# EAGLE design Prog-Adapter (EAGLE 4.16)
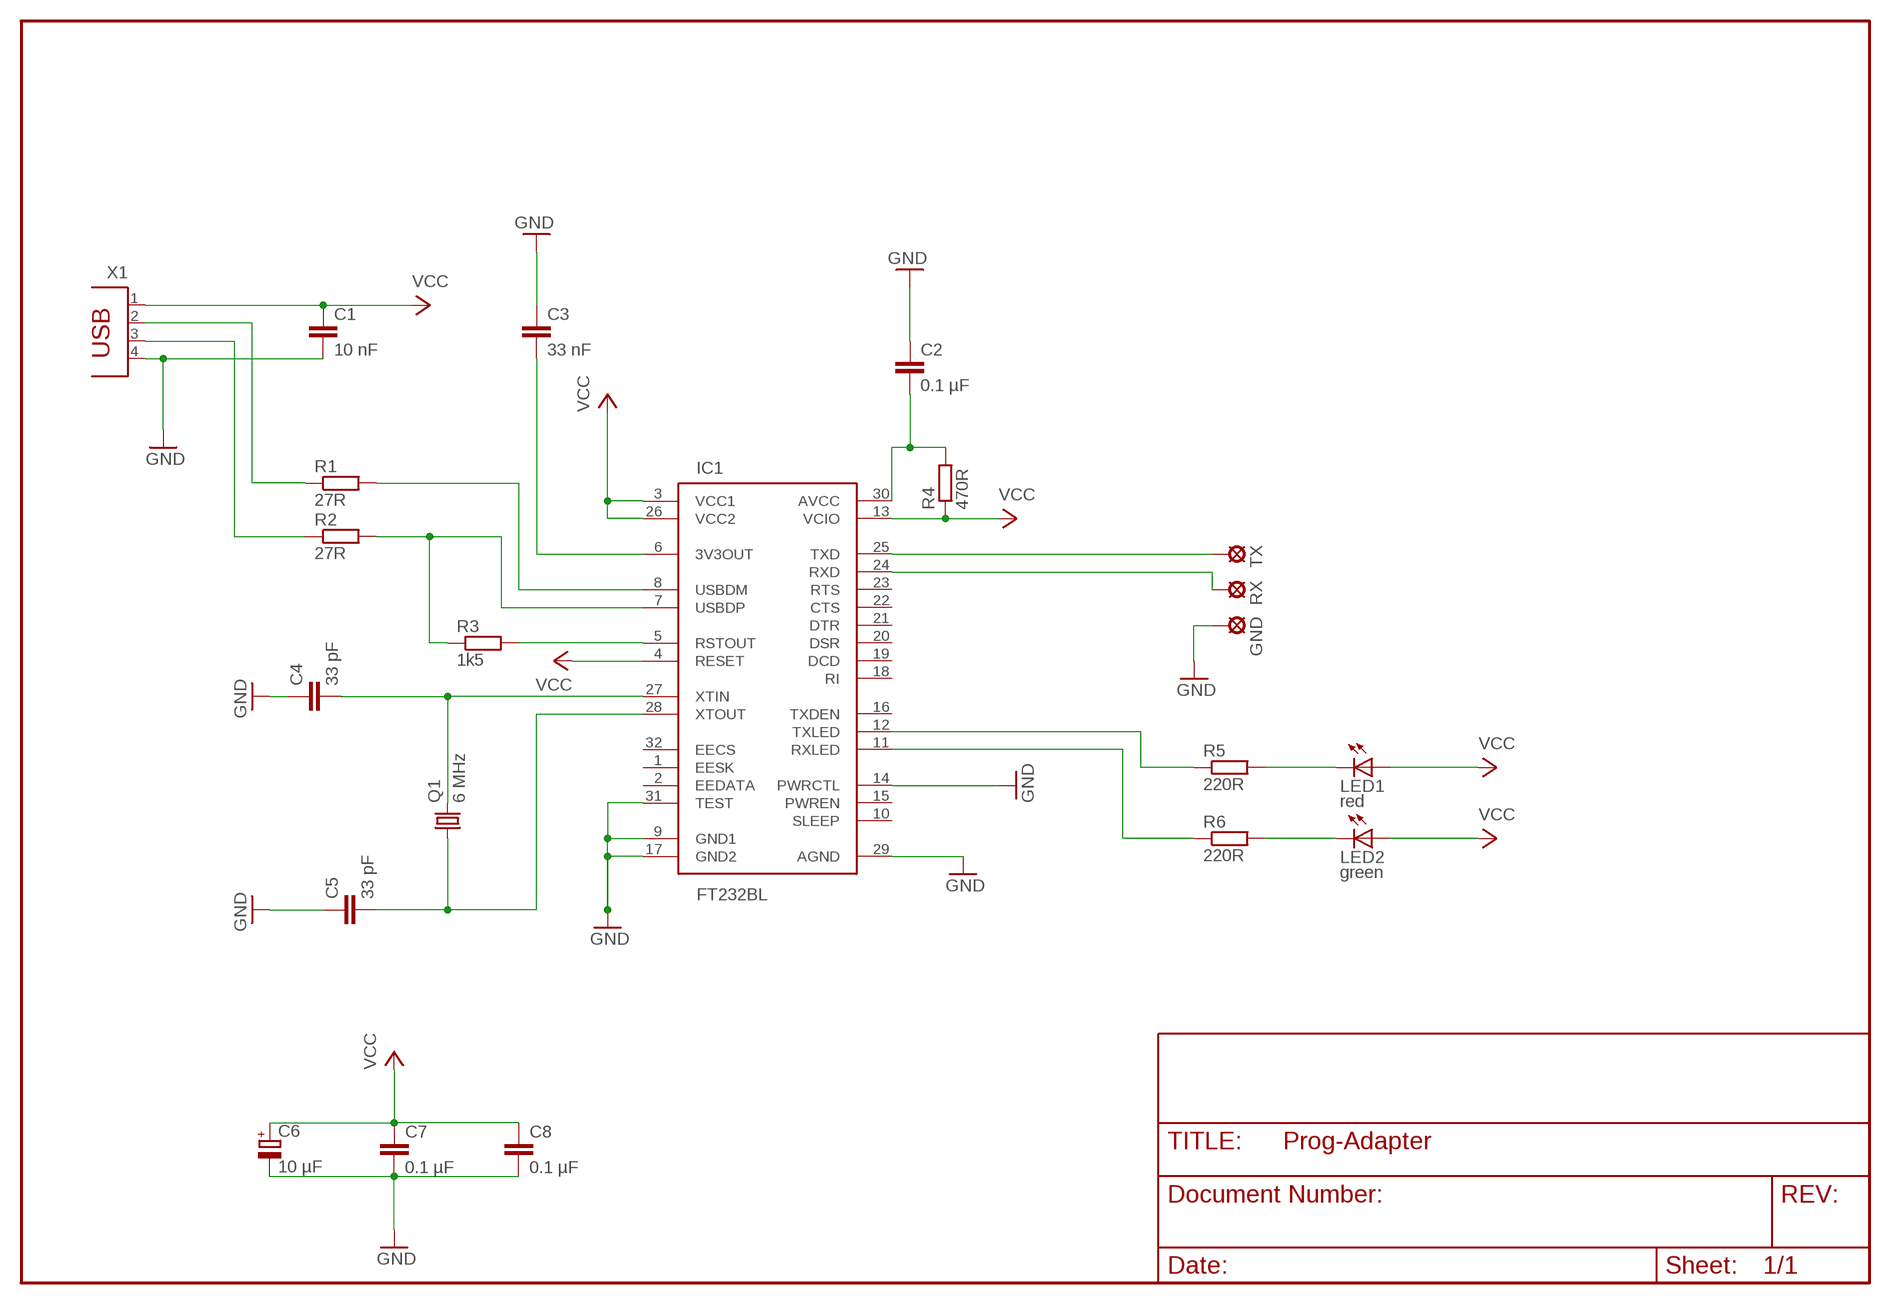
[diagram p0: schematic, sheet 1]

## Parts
C1  10 nF  C-EUC1206  [C1206]
C2  0.1 µF  C-EUC1206  [C1206]
C3  33 nF  C-EUC1206  [C1206]
C4  33 pF  C-EUC1206  [C1206]
C5  33 pF  C-EUC1206  [C1206]
C6  10 µF  CPOL-EUSMCC  [SMC_C]
C7  0.1 µF  C-EUC1206  [C1206]
C8  0.1 µF  C-EUC1206  [C1206]
GND  LSP10  [LSP10]
IC1  FT232BL  FT232BM  [QFP-32]
LED1  red  LED3MM  [LED3MM]
LED2  green  LED3MM  [LED3MM]
Q1  6 MHz  CRYTALHC49S  [HC49/S]
R1  27R  R-EU_M1206  [M1206]
R2  27R  R-EU_M1206  [M1206]
R3  1k5  R-EU_M1206  [M1206]
R4  470R  R-EU_M1206  [M1206]
R5  220R  R-EU_M1206  [M1206]
R6  220R  R-EU_M1206  [M1206]
RX  LSP10  [LSP10]
TX  LSP10  [LSP10]
X1  PN61729  [PN61729]

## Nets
GND: C1.2 C2.1 C3.1 C4.1 C5.1 C6.- C7.2 C8.2 GND.MP IC1.9(GND1) IC1.14(PWRCTL) IC1.17(GND2) IC1.29(AGND) IC1.31(TEST) X1.4
N$1: IC1.24(RXD) RX.MP
N$2: IC1.25(TXD) TX.MP
N$3: IC1.8(USBDM) R1.2
N$4: R2.1 X1.3
N$5: R1.1 X1.2
N$6: IC1.7(USBDP) R2.2 R3.1
N$7: IC1.5(RSTOUT) R3.2
N$8: C2.2 IC1.30(AVCC) R4.2
N$9: C3.2 IC1.6(3V3OUT)
N$10: C4.2 IC1.27(XTIN) Q1.2
N$11: LED1.K(C) R5.2
N$12: C5.2 IC1.28(XTOUT) Q1.1
N$13: LED2.K(C) R6.2
N$14: IC1.12(TXLED) R5.1
N$15: IC1.11(RXLED) R6.1
VCC: C1.1 C6.+ C7.1 C8.1 IC1.3(VCC1) IC1.4(RESET) IC1.13(VCIO) IC1.26(VCC2) LED1.A LED2.A R4.1 X1.1
Unconnected: IC1.1(EESK) IC1.2(EEDATA) IC1.10(SLEEP) IC1.15(PWREN) IC1.16(TXDEN) IC1.18(RI) IC1.19(DCD) IC1.20(DSR) IC1.21(DTR) IC1.22(CTS) IC1.23(RTS) IC1.32(EECS)

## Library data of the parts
C1-C5 C7 C8 = rcl:C-EU: CAPACITOR, European symbol
C6 = rcl:CPOL-EU: POLARIZED CAPACITOR, European symbol
GND RX TX = solpad:LSP10: SOLDER PAD
IC1 = FTDI:FT232BM: FT232BM USB-RS232 Wandler FTDI
LED1 LED2 = led:LED: LED
Q1 = crystal:CRYTAL: CRYSTAL
R1-R6 = rcl:R-EU_: RESISTOR, European symbol
X1 = con-berg:PN61729: BERG USB connector

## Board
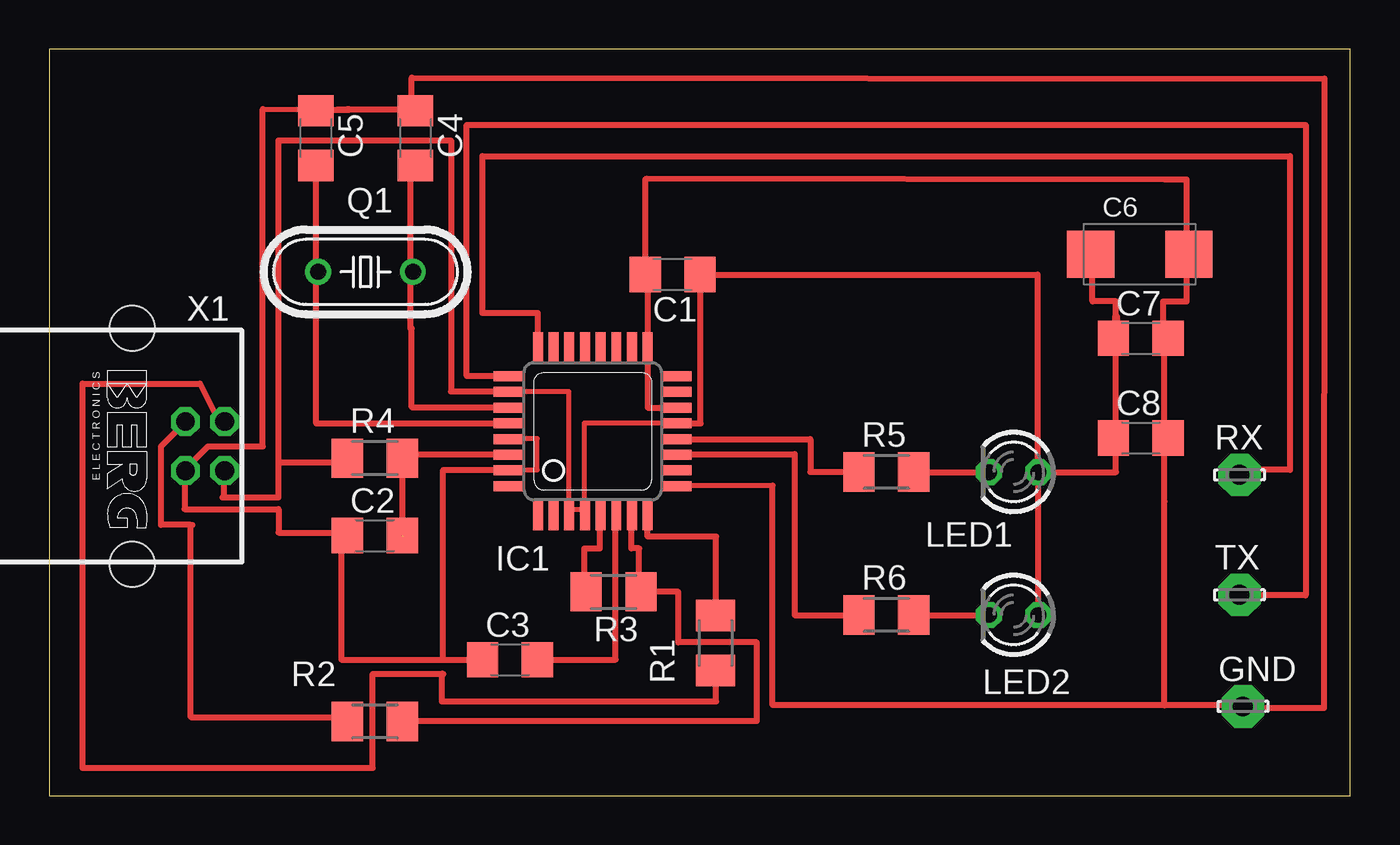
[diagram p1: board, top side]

Size 66.4 x 38.08 mm. Coordinates in mm from the lower left corner, seen from the top.
Outline: 0,0 66.4,0 66.4,38.08 0,38.08 0,0
Copper layers (1*16): Top 0.035mm / dielectric 1.5mm / Bottom 0.035mm
Design rules "default": minimum track width 10mil, minimum drill 24mil, track to track 8mil, track to pad 8mil, pad to pad 8mil, via to via 8mil, smd to smd 8mil, copper to edge 40mil, drill to drill 8mil, minimum pad ring 10mil, minimum via ring 8mil, stop-mask expansion 4mil, vias tented up to drill 0mil, thermal gap 10mil

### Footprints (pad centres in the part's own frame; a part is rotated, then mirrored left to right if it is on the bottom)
C1206 = smd 1.6 x 1.8: 1 -1.4,0; 2 1.4,0
SMC_C = smd 2.4 x 2.4: + -2.5,0; - 2.5,0
LSP10 = drill 1.016 pad 2.159 octagon: MP 0,0
QFP-32 = smd 0.508 x 1.6: 1 -2.8,-4.25; 2 -2,-4.25; 3 -1.2,-4.25; 4 -0.4,-4.25; 5 0.4,-4.25; 6 1.2,-4.25; 7 2,-4.25; 8 2.8,-4.25; 17 2.8,4.25; 18 2,4.25; 19 1.2,4.25; 20 0.4,4.25; 21 -0.4,4.25; 22 -1.2,4.25; 23 -2,4.25; 24 -2.8,4.25 | smd 1.6 x 0.508: 9 4.25,-2.8; 10 4.25,-2; 11 4.25,-1.2; 12 4.25,-0.4; 13 4.25,0.4; 14 4.25,1.2; 15 4.25,2; 16 4.25,2.8; 25 -4.25,2.8; 26 -4.25,2; 27 -4.25,1.2; 28 -4.25,0.4; 29 -4.25,-0.4; 30 -4.25,-1.2; 31 -4.25,-2; 32 -4.25,-2.8
LED3MM = drill 0.813 octagon: A -1.27,0; K 1.27,0
HC49/S = drill 0.813 round: 1 -2.413,0; 2 2.413,0
M1206 = smd 1.6 x 2: 1 -1.4,0; 2 1.4,0
PN61729 = drill 0.95 octagon: 1 1.25,4.71; 2 -1.25,4.71; 3 -1.25,2.71; 4 1.25,2.71 | hole 2.3: -6.02,0; 6.02,0

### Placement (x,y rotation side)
C1  31.81,26.58 180 top
C2  16.62,13.27 0 top
C3  23.52,6.94 0 top
C4  18.69,33.54 270 top
C5  13.61,33.54 270 top
C6  55.64,27.61 0 top
C7  55.7,23.33 0 top
C8  55.7,18.25 0 top
GND  60.91,4.55 0 top
IC1  27.74,18.59 0 top
LED1  49.21,16.51 180 top
LED2  49.21,9.22 180 top
Q1  16.15,26.72 0 top
R1  34,7.79 90 top
R2  16.62,3.79 0 top
R3  28.8,10.4 180 top
R4  16.62,17.22 0 top
R5  42.72,16.51 0 top
R6  42.72,9.22 0 top
RX  60.73,16.37 0 top
TX  60.73,10.25 0 top
X1  4.25,17.83 270 top

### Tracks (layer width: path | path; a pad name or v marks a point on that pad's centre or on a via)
GND
  Top 0.254: IC1.9 32.51,15.82 36.91,15.82 | 56.91,23.42 C7.2 | IC1.29 24.11,18.22 24.91,18.22 24.91,16.62 24.11,16.62 IC1.31 22.91,16.62 | C5.1 15.31,34.94 15.31,35.02 10.91,35.02 | 7.31,17.02 X1.4 6.91,16.58 | C2.1 14.51,13.42 | C2.1 14.91,12.62 | C2.1 14.91,13.27 14.91,13.42
  Top 0.305: 36.91,15.82 36.91,4.62 56.91,4.62 56.91,4.61 | C7.2 56.91,23.33 56.91,23.42 | 56.91,23.42 56.91,23.82 | 56.91,18.25 C8.2 | 56.91,18.25 56.91,23.42 | 56.91,4.61 56.91,18.25 | 56.91,4.61 56.91,15.02 | C4.1 18.69,35.02 18.51,35.02 | C5.1 15.21,35.02 15.31,35.02 18.51,35.02 | 18.51,35.02 18.51,36.62 65.07,36.57 65.05,4.46 60.96,4.46 60.96,4.55 | 22.91,16.62 20.11,16.62 20.11,6.94 | 10.91,35.02 10.91,17.82 8.11,17.82 7.31,17.02 | 20.11,6.94 14.91,6.94 14.91,12.62 | 6.91,16.58 6.91,14.62 11.71,14.62 11.71,13.42 14.91,13.42 | IC1.17 30.51,22.84 | 56.84,23.82 56.84,25.21 58.04,25.21 58.04,27.61 58.04,31.42 56.91,31.42 30.52,31.45 30.42,31.43 30.41,31.43 C1.2 | 22.04,6.94 22.04,6.81 | 22.04,6.94 C3.1 | 20.11,6.94 22.04,6.94 | 60.95,4.61 60.95,4.55 GND.MP 60.96,4.55 | 60.95,4.61 56.91,4.61 | 60.95,4.61 60.95,4.66 | 60.96,4.55 60.96,4.56 | IC1.17 30.54,22.99 | IC1.17 | IC1.14 30.54,19.79 IC1.17 | IC1.17 30.56,22.84 | IC1.17 30.54,26.58 C1.2 | C1.2
  Top 0.406: 56.91,23.82 56.84,23.82 | 58.04,27.61 C6.-
N$1
  Top 0.305: IC1.24 24.94,24.62 22.11,24.62 22.11,32.62 63.31,32.62 63.31,16.62 60.73,16.62 RX.MP
N$2
  Top 0.305: IC1.25 23.49,21.42 21.31,21.42 21.31,34.22 64.11,34.22 64.11,10.22 60.73,10.22 TX.MP
N$3
  Top 0.305: IC1.8 30.54,13.21 34.04,13.21 34.04,9.21 34,9.21 R1.2
N$4
  Top 0.254: 5.71,16.62 5.71,16.22
  Top 0.305: X1.3 6.51,18.62 5.71,17.82 5.71,16.62 5.71,13.82 7.24,13.82 | R2.1 15.22,4.01 7.24,4.01 7.24,13.82 | 7.24,13.82 7.31,13.82
N$5
  Top 0.305: 20.04,6.22 16.51,6.22 16.51,1.42 1.71,1.42 1.71,21.02 7.71,21.02 8.51,19.42 X1.2 | R1.1 34.04,6.39 34.04,4.81 20.04,4.81 20.04,6.22 | 20.11,6.22 20.04,6.22
N$6
  Top 0.305: IC1.7 29.71,14.34 29.71,12.62 30.11,12.62 30.11,11.2 R3.1 32.11,10.4 32.11,7.82 36.11,7.82 36.11,7.61 | 36.11,7.61 36.11,3.82 18.04,3.82 | 36.11,7.61 36.11,7.64 | 18.04,3.82 18.04,3.79 R2.2 | 18.04,3.82 18.04,4.01
N$7
  Top 0.305: IC1.5 28.11,14.34 28.11,12.62 27.31,12.62 27.31,11.2 R3.2
N$8  (1 unrouted)
  Top 0.254: 22.91,17.42 IC1.30 | C2.2 18.51,13.82
  Top 0.305: 18.44,17.42 18.51,17.42 | 18.51,13.82 18.44,13.82 | 18.04,17.22 18.04,17.21 | 18.04,17.22 R4.2 | 18.44,17.42 22.91,17.42 | 18.04,17.42 18.04,17.22 | 18.04,17.42 18.44,17.42 | 18.04,13.21 18.04,17.42
N$9
  Top 0.305: IC1.6 28.91,14.34 28.91,6.94 C3.2
N$10
  Top 0.305: IC1.27 23.49,19.82 18.51,19.82 18.51,23.82 18.44,23.82 18.44,26.72 | C4.2 18.44,32.14 18.44,26.72 | 18.44,26.72 Q1.2
N$11
  Top 0.305: R5.2 LED1.K
N$12
  Top 0.305: 13.64,26.72 13.64,26.81 | IC1.28 13.64,18.99 13.64,26.72 | C5.2 13.64,32.14 13.64,26.72 | 13.64,26.72 Q1.1
N$13
  Top 0.305: 47.64,9.22 LED2.K | R6.2 47.64,9.22 | 47.64,9.22 47.64,9.21
N$14
  Top 0.305: IC1.12 38.85,18.19 38.85,16.52 41.24,16.52 41.24,16.51 | 41.24,16.51 41.24,16.46 | 41.24,16.51 R5.1
N$15
  Top 0.305: IC1.11 32.11,17.39 32.11,17.42 38.04,17.42 38.04,9.21 41.24,9.21 41.24,9.22 R6.1
VCC
  Top 0.254: 25.71,20.62 24.11,20.62 IC1.26 22.91,20.62 | 25.71,20.62 26.11,20.62 | IC1.13 31.31,19.02 27.31,19.02 27.31,15.02 IC1.4 27.31,14.62 26.51,14.62 IC1.3 26.51,15.02 26.51,20.62 25.71,20.62
  Top 0.305: X1.1 8.91,16.22 8.91,15.21 | 22.91,20.62 20.51,20.62 20.51,33.42 11.71,33.42 11.71,17.02 | 53.24,27.61 53.24,25.21 54.44,25.21 54.44,24.41 54.44,18.25 | 50.44,16.51 50.44,16.41 | 50.44,9.22 50.44,8.81 | 50.44,9.22 LED2.A | LED1.A 50.44,16.51 | 50.44,16.51 50.44,9.22 | LED1.A 54.44,16.51 54.44,18.25 | 54.44,18.25 C8.1 | R4.1 14.84,17.22 14.84,17.02 11.71,17.02 | 8.91,15.21 8.84,15.21 | 11.71,17.02 11.71,15.21 8.91,15.21 | 33.24,26.58 33.24,26.81 | IC1.13 33.24,18.99 | 50.43,16.51 50.43,16.41 | 50.43,16.51 LED1.A | 33.24,26.58 C1.1 | 33.24,26.58 50.43,26.58 50.43,16.51 | 33.24,18.99 | 33.24,18.99 | 33.24,26.58 33.24,18.99
  Top 0.406: C7.1 54.44,23.33 54.44,24.41 | 53.24,27.61 C6.+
